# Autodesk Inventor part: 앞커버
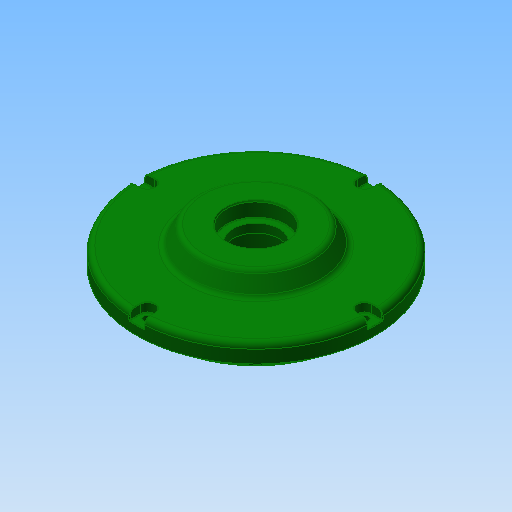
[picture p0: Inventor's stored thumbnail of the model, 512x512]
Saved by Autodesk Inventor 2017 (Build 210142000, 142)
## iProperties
Created: 2016-11
Part Number: 앞커버
Material: 알루미늄 6061
Document SubType Name: Modeling
Designer: mduedu
Density: 2.71 g/cm^3
Mass: 470.683 g
Surface Area: 413.208 cm^2
Volume: 173.684 cm^3
Appearance: 진녹색
Author: mduedu
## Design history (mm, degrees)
sketch "스케치1"
  geometry: L1 (30, -16)-(30, -30); L2 (30, -30)-(20, -35.774); L3 (20, -35.774)-(20, -65); L4 (20, -65)-(10, -65); L5 (10, -65)-(10, -53); L6 (10, -53)-(0, -53); L7 (0, -53)-(0, -23.5); L8 (0, 0)-(30, 0); L9 (14, -23.5)-(14, -20.5); L10 (14, -20.5)-(17, -20.5); L11 (17, -20.5)-(17, -12.5); L12 (0, -23.5)-(14, -23.5); L13 (21.7, -16)-(30, -16); L14 (21.7, -16)-(21.7, -12.5); L15 (21.7, -12.5)-(17, -12.5)
  constraints: 30 end point, 8 parallel, 5 perpendicular, 2 horizontal, 2 vertical alignment
  dimensions: "d0" = 10 distance of L5.end L6.end; "d2" = 10 distance of L3.end L4.end; "d3" = 10 distance between parallel lines of L1 L3; "d4" = 120 deg angle of L3 L2; "d6" = 60 diameter of L1.end L8; "d7" = 41 diameter of L10 L8; "d8" = 47 diameter of L12 L8; "d9" = 32 diameter of L13 L8; "d10" = 106 diameter of L6 L8; "d11" = 130 diameter of L4 L8; "d64" = 14 distance between parallel lines of L9 L7; "d65" = 3 distance of L9.end L10.end; "d66" = 8.3 distance of L13.start L1.start; "d67" = 25 diameter of L15 L8
revolve "회전1" sketch "스케치1" stored, may be unused: angle "d12" = 90 deg
fillet "모깎기1" dims "d13" = 1
fillet "모깎기2" dims "d14" = 3
chamfer "모따기1" distance "d15" = 1; stored, may be unused: second distance "d16" = 2, angle "d17" = 45 deg
fillet "모깎기3" dims "d18" = 0.3
chamfer "모따기2" distance "d36" = 0.8; stored, may be unused: second distance "d37" = 2, angle "d38" = 30 deg
sketch "스케치3"
  geometry: C1 r 65 at (0, 0) reference; A1 r 59 centre (0, 0) between (0, 59) and (59, 0); 2 further points
  constraints: 4 point on circle, 2 horizontal alignment, 2 vertical alignment, 1 centre point, 1 coincident
  dimensions: "d33" = 118 diameter of A1
sketch "스케치4"
  geometry: 4 further points
  constraints: 4 other
hole "구멍2" sketch "스케치4" at (0, 59), (-59, 0), (59, 0), (0, -59) diameter "d39" = 4.5; stored, may be unused: countersink angle "d43" = 90 deg, drill point angle "d45" = 0 deg; dims "d40" = 6, "d41" = 8, "d42" = 5, "d44" = 8
sketch "스케치6"
  geometry: L1 (-4, 5.877)-(-4, 0); L2 (4, 5.877)-(4, 0); A1 r 4 centre (0, 0) between (-2.712, 2.941) and (2.712, 2.941) reference; A2 r 65 centre (0, -59) between (-4, 5.877) and (4, 5.877) reference; 1 further point
  constraints: 4 end point, 4 point on circle, 2 tangent, 2 vertical
extrude "돌출2" cut sketch "스케치6" stored distance "d51" = 10; taper "d52" = 0 deg
fillet "모깎기5" dims "d56" = 0.3
fillet "모깎기6" dims "d57" = 0.3
sketch "스케치5"
  geometry: C1 r 30 at (0, 0); C2 r 47.5 at (0, 0); 1 further point
  constraints: 2 centre point, 2 coincident
  dimensions: "d46" = 60 diameter of C1; "d47" = 95 diameter of C2
extrude "돌출1" cut sketch "스케치5" distance "d48" = 10; taper "d49" = 0 deg
fillet "모깎기4" dims "d50" = 3
node "솔리드1"
pattern_circular "원형 패턴1" dims angle "d54" = 360 deg
pattern_circular "원형 패턴2" dims angle "d59" = 360 deg
pattern_circular "원형 패턴3" dims angle "d62" = 360 deg
